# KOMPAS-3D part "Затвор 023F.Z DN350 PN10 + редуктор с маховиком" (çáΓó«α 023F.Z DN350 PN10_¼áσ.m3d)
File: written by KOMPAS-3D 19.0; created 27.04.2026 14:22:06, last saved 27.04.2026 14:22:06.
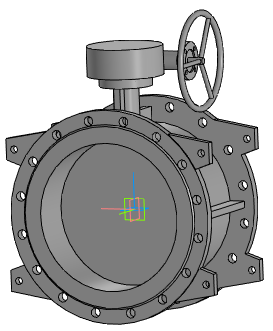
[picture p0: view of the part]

Document properties: Полное имя файла: ..\..\Затвор 023F.Z DN200-DN1600_с маховиком\Затвор 023F.Z DN350 PN10 + редуктор с маховиком.a3d

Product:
- Part/product: Затвор 023F.Z DN350 PN10 + редуктор с маховиком
    Масса: 128.044

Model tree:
1. Операция без истории:1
